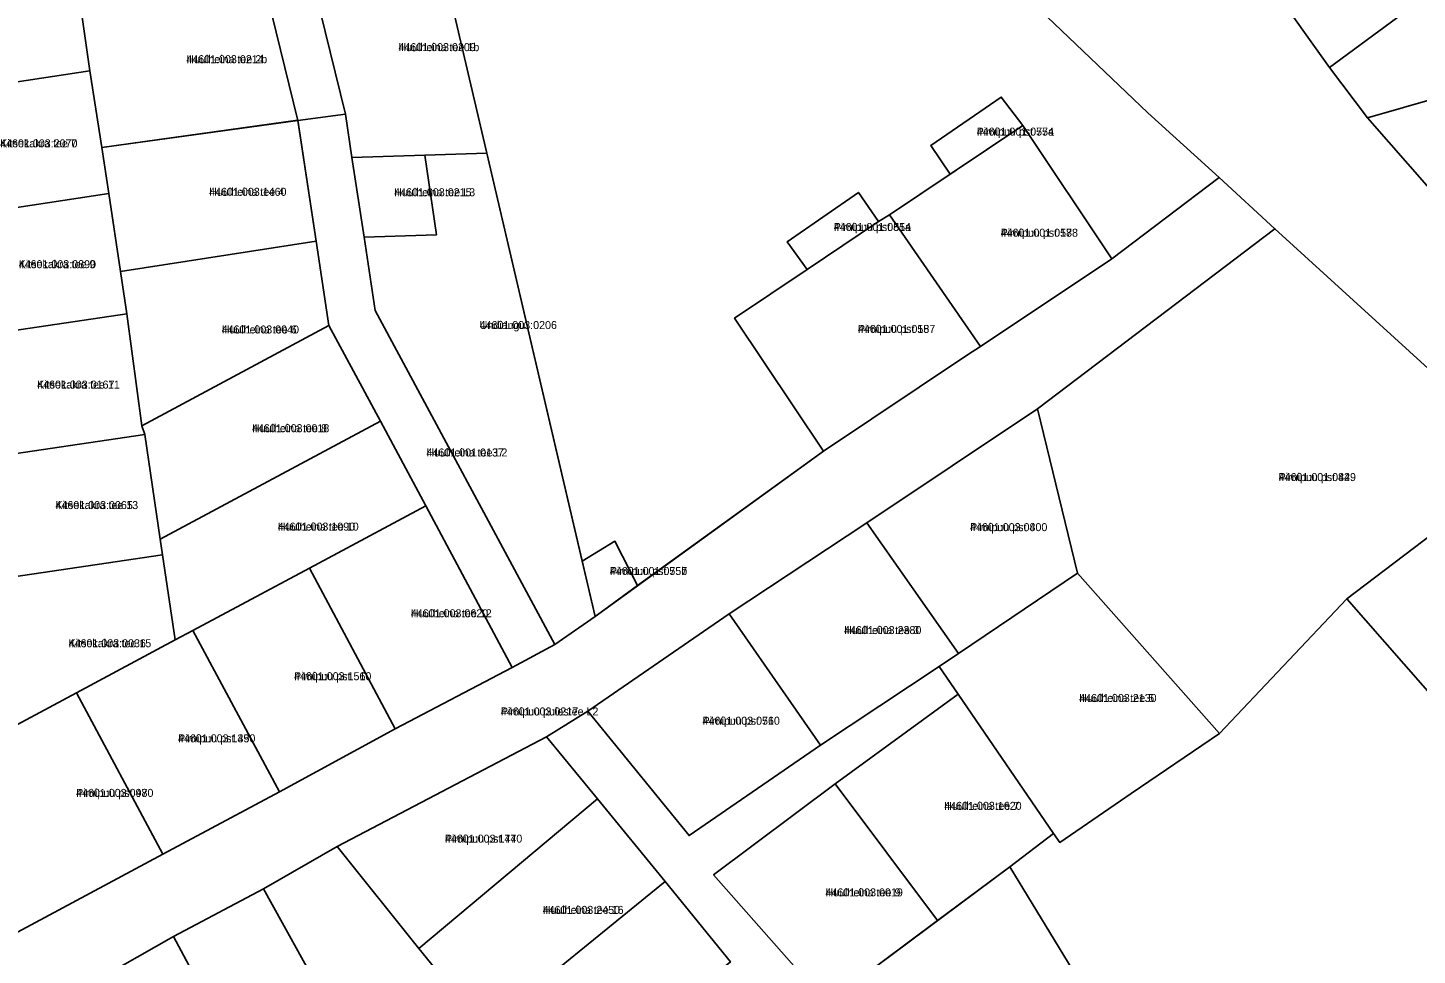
# Model space of a CAD drawing. Extents: x 551843 to 558501, y 6589003 to 6595718.
# Drawn here: x 553458.8 to 553719.3, y 6593624.3 to 6593798.2 of the extents above; entities that cross this region are included whole.
import ezdxf

# ---------------------------------------------------------------- set-up
doc = ezdxf.new("R2010")
doc.units = 0
for name, color, linetype in [('L_AADRESS', 7, 'Continuous'), ('PIIR', 7, 'Continuous'), ('TUNNUS', 7, 'Continuous')]:
    doc.layers.add(name, color=color, linetype=linetype)

msp = doc.modelspace()

# ---------------------------------------------------------------- linework, layer by layer
at = {"layer": 'PIIR'}
for points in [[(553514.88, 6593903.23), (553507.01, 6593937.53), (553542.86, 6593955.37), (553636.48, 6593813.23), (553668.84, 6593782.29), (553682.2, 6593770.11), (553662.08, 6593754.91), (553645.43, 6593779.86), (553641.35, 6593785.23), (553628.15, 6593776.12), (553631.77, 6593770.74), (553620.41, 6593763.16), (553618.37, 6593761.87), (553614.56, 6593767.34), (553601.23, 6593758.1), (553604.99, 6593752.88), (553591.37, 6593743.76), (553608.02, 6593718.81), (553573.18, 6593693.61), (553568.93, 6593701.92), (553562.79, 6593698.22), (553544.92, 6593774.7), (553535.42, 6593815.33), (553523, 6593868.46)], [(553492.7, 6593835.84), (553497.56, 6593844.41), (553505.32, 6593846.51), (553509.29, 6593831.88), (553506.64, 6593830.09), (553511.74, 6593809.27), (553518.39, 6593782.01), (553509.5, 6593780.83), (553502.99, 6593807.38), (553497.7, 6593828.94), (553494.74, 6593828.32)], [(553692.18, 6593805.9), (553712.78, 6593821.28), (553730.01, 6593834.09), (553741.11, 6593818.98), (553702.89, 6593790.78)], [(553741.11, 6593818.98), (553758.61, 6593795.24), (553710.04, 6593781.31), (553702.89, 6593790.78)], [(553535.42, 6593815.33), (553544.92, 6593774.7), (553533.27, 6593774.3), (553519.62, 6593773.88), (553518.39, 6593782.01), (553511.74, 6593809.27)], [(553430.62, 6593806.89), (553467.23, 6593812.98), (553468.8, 6593801.92), (553470.45, 6593790.14), (553433.32, 6593784.52)], [(553502.99, 6593807.38), (553509.5, 6593780.83), (553472.74, 6593775.77), (553470.45, 6593790.14), (553468.8, 6593801.92)], [(553470.45, 6593790.14), (553472.74, 6593775.77), (553474.02, 6593767.15), (553436.6, 6593761.45), (553433.32, 6593784.52)], [(553645.43, 6593779.86), (553631.77, 6593770.74), (553628.15, 6593776.12), (553641.35, 6593785.23)], [(553509.49, 6593780.87), (553512.89, 6593758.2), (553476.25, 6593752.53), (553474.02, 6593767.15), (553472.74, 6593775.77)], [(553512.89, 6593758.2), (553509.5, 6593780.83), (553518.39, 6593782.01), (553519.62, 6593773.88), (553521.89, 6593758.95), (553523.96, 6593745.19), (553557.67, 6593682.56), (553549.67, 6593678.28), (553533.46, 6593708.56), (553524.95, 6593724.42), (553515.3, 6593742.41)], [(553662.08, 6593754.91), (553637.47, 6593738.47), (553620.41, 6593763.16), (553645.43, 6593779.86)], [(553533.27, 6593774.3), (553535.46, 6593759.37), (553521.89, 6593758.95), (553519.62, 6593773.88)], [(553533.27, 6593774.3), (553544.92, 6593774.7), (553565.22, 6593687.84), (553557.67, 6593682.56), (553523.96, 6593745.19), (553521.89, 6593758.95), (553535.46, 6593759.37)], [(553436.6, 6593761.45), (553474.02, 6593767.15), (553476.25, 6593752.53), (553477.43, 6593744.57), (553440.63, 6593739.12)], [(553604.99, 6593752.88), (553601.23, 6593758.1), (553614.56, 6593767.34), (553618.37, 6593761.87)], [(553620.41, 6593763.16), (553637.47, 6593738.47), (553635.05, 6593736.86), (553608.02, 6593718.81), (553591.37, 6593743.76), (553604.99, 6593752.88), (553618.37, 6593761.87)], [(553648.17, 6593726.77), (553692.68, 6593760.54), (553740.33, 6593717.08), (553706.18, 6593691.1), (553682.25, 6593665.88), (553655.66, 6593695.97)], [(553512.89, 6593758.2), (553515.3, 6593742.41), (553480.21, 6593723.58), (553477.43, 6593744.57), (553476.25, 6593752.53)], [(553443.97, 6593716.53), (553440.63, 6593739.12), (553477.43, 6593744.57), (553480.21, 6593723.58), (553480.76, 6593721.97)], [(553480.76, 6593721.97), (553480.21, 6593723.58), (553515.3, 6593742.41), (553524.95, 6593724.42), (553483.66, 6593702.32)], [(553655.66, 6593695.97), (553633.31, 6593680.87), (553616.16, 6593705.37), (553648.17, 6593726.77)], [(553533.46, 6593708.56), (553511.64, 6593696.87), (553489.8, 6593685.2), (553486.46, 6593683.41), (553484.1, 6593699.37), (553483.66, 6593702.32), (553524.95, 6593724.42)], [(553443.97, 6593716.53), (553480.76, 6593721.97), (553483.66, 6593702.32), (553484.1, 6593699.37), (553447.31, 6593693.94)], [(553706.18, 6593691.1), (553740.33, 6593717.08), (553760.4, 6593695.25), (553727.55, 6593666.75)], [(553527.71, 6593666.74), (553511.64, 6593696.87), (553533.46, 6593708.56), (553549.67, 6593678.28)], [(553590.37, 6593688.32), (553616.16, 6593705.37), (553633.31, 6593680.87), (553629.72, 6593678.45), (553607.45, 6593663.66)], [(553565.22, 6593687.84), (553562.79, 6593698.22), (553568.93, 6593701.92), (553573.18, 6593693.6)], [(553484.1, 6593699.37), (553486.46, 6593683.41), (553467.99, 6593673.52), (553451.6, 6593664.73), (553447.31, 6593693.94)], [(553527.71, 6593666.74), (553506.01, 6593654.92), (553489.8, 6593685.2), (553511.64, 6593696.87)], [(553633.31, 6593680.87), (553655.66, 6593695.97), (553682.25, 6593665.88), (553665.73, 6593654.61), (553652.31, 6593645.45), (553651.15, 6593647.15), (553634.23, 6593671.86), (553629.72, 6593678.45)], [(553642.95, 6593640.9), (553651.15, 6593647.15), (553652.31, 6593645.45), (553665.73, 6593654.61), (553682.25, 6593665.88), (553706.18, 6593691.1), (553727.55, 6593666.75), (553740.49, 6593651.51), (553753.74, 6593636.43), (553762.31, 6593626.44), (553803.44, 6593644.47), (553829.2, 6593610.91), (553852.28, 6593578.7), (553731.4, 6593518.62), (553696.7, 6593564.49), (553681.11, 6593583.74), (553684.34, 6593586.4), (553671.35, 6593603.22), (553668.55, 6593601.29), (553655.51, 6593620.23)], [(553607.45, 6593663.66), (553582.84, 6593646.72), (553563.86, 6593670.06), (553590.37, 6593688.32)], [(553484.19, 6593643.24), (553467.99, 6593673.52), (553486.46, 6593683.41), (553489.8, 6593685.2), (553506.01, 6593654.92)], [(553456.92, 6593628.62), (553451.6, 6593664.73), (553467.99, 6593673.52), (553484.19, 6593643.24)], [(553633.29, 6593673.23), (553651.15, 6593647.15), (553642.95, 6593640.9), (553629.39, 6593630.84), (553610.19, 6593656.43)], [(553565.66, 6593653.61), (553532.13, 6593625.56), (553516.86, 6593644.69), (553556.12, 6593665.26)], [(553610.19, 6593656.43), (553629.39, 6593630.84), (553608.64, 6593615.29), (553587.41, 6593639.36)], [(553565.66, 6593653.61), (553578.32, 6593638.11), (553544.39, 6593610.49), (553532.13, 6593625.56)], [(553503.05, 6593636.73), (553516.86, 6593644.69), (553532.13, 6593625.56), (553544.39, 6593610.49), (553545.17, 6593609.54), (553530.83, 6593601.86), (553524.02, 6593598.81)], [(553642.95, 6593640.9), (553655.51, 6593620.23), (553622.78, 6593597.69), (553608.64, 6593615.29)], [(553545.17, 6593609.54), (553544.39, 6593610.49), (553578.32, 6593638.11), (553590.58, 6593623.04), (553556.65, 6593595.42)], [(553503.05, 6593636.73), (553524.02, 6593598.81), (553512.47, 6593592.6), (553506.67, 6593589.45), (553486.18, 6593627.79)], [(553469.35, 6593618.26), (553486.18, 6593627.79), (553506.67, 6593589.45), (553495.03, 6593582.69), (553489.88, 6593579.92)]]:
    msp.add_lwpolyline(points, close=True, dxfattribs=at)
for points in [[(553692.18, 6593805.9), (553702.89, 6593790.78), (553710.04, 6593781.31), (553721.57, 6593768.11), (553784.72, 6593695.82), (553773.88, 6593783.39), (553783.85, 6593784.58), (553786.09, 6593767.59), (553788.55, 6593748.98), (553791.01, 6593730.37), (553793.55, 6593711.51), (553796.03, 6593693.39), (553797.95, 6593674), (553801.52, 6593668.77), (553816.61, 6593652.09), (553803.44, 6593644.47), (553786.46, 6593665.16), (553772.78, 6593680.33), (553760.4, 6593695.25), (553740.33, 6593717.08), (553692.68, 6593760.54), (553682.2, 6593770.11), (553668.84, 6593782.29), (553636.48, 6593813.23)], [(553721.57, 6593768.11), (553710.04, 6593781.31), (553758.61, 6593795.24)], [(553456.92, 6593628.62), (553484.19, 6593643.24), (553506.01, 6593654.92), (553527.71, 6593666.74), (553549.67, 6593678.28), (553557.67, 6593682.56), (553565.22, 6593687.84), (553608.02, 6593718.81), (553635.05, 6593736.86), (553637.47, 6593738.47), (553662.08, 6593754.91), (553682.2, 6593770.11), (553692.68, 6593760.54), (553648.17, 6593726.77), (553616.16, 6593705.37), (553590.37, 6593688.32), (553563.86, 6593670.06), (553556.12, 6593665.26), (553516.86, 6593644.69), (553503.05, 6593636.73), (553486.18, 6593627.79), (553469.35, 6593618.26)], [(553590.58, 6593623.04), (553578.32, 6593638.11), (553565.66, 6593653.61), (553556.12, 6593665.26), (553563.86, 6593670.06), (553582.84, 6593646.72), (553607.45, 6593663.66), (553629.72, 6593678.45), (553633.29, 6593673.23), (553610.19, 6593656.43), (553587.41, 6593639.36), (553608.64, 6593615.29)]]:
    msp.add_lwpolyline(points, dxfattribs=at)

# ---------------------------------------------------------------- texts
at = {"layer": 'L_AADRESS'}
for s, p in [('Huulheina tee 1b', (553528.33, 6593793.83)), ('Huulheina tee 2b', (553488.56, 6593791.57)), ('Pirnipuu pst 57a', (553636.74, 6593777.99)), ('Kitsekakra tee 7', (553453.65, 6593775.79)), ('Huulheina tee 4', (553492.85, 6593766.7)), ('Huulheina tee L3', (553527.54, 6593766.62)), ('Pirnipuu pst 55a', (553609.94, 6593760.11)), ('Pirnipuu pst 57', (553641.24, 6593759.03)), ('Kitsekakra tee 9', (553457.13, 6593753.13)), ('Huulheina tee 6', (553495.19, 6593740.89)), ('Undiaugu', (553543.55, 6593741.72)), ('Pirnipuu pst 55', (553614.48, 6593740.99)), ('Kitsekakra tee 11', (553460.59, 6593730.55)), ('Huulheina tee 8', (553500.87, 6593722.37)), ('Huulheina tee L2', (553533.59, 6593717.82)), ('Pirnipuu pst 82', (553693.36, 6593713.21)), ('Kitsekakra tee 13', (553464.03, 6593707.96)), ('Huulheina tee 10', (553505.71, 6593703.92)), ('Pirnipuu pst 80', (553635.5, 6593703.82)), ('Pirnipuu pst 55b', (553567.98, 6593695.6)), ('Huulheina tee 12', (553530.66, 6593687.67)), ('Huulheina tee 3', (553611.88, 6593684.52)), ('Kitsekakra tee 15', (553466.49, 6593682.05)), ('Pirnipuu pst 51', (553508.75, 6593675.87)), ('Huulheina tee 5', (553655.98, 6593671.78)), ('Pirnipuu puiestee L2', (553547.54, 6593669.26)), ('Pirnipuu pst 76', (553585.35, 6593667.52)), ('Pirnipuu pst 49', (553487, 6593664.22)), ('Pirnipuu pst 47', (553467.89, 6593653.99)), ('Huulheina tee 7', (553630.67, 6593651.56)), ('Pirnipuu pst 74', (553537.05, 6593645.41)), ('Huulheina tee 9', (553608.4, 6593635.33)), ('Huulheina tee 16', (553555.38, 6593632.05))]:
    msp.add_text(s, height=1.5, dxfattribs=at).set_placement(p)
at = {"layer": 'TUNNUS'}
for s, p in [('44601:003:0209', (553528.33, 6593793.83)), ('44601:003:0214', (553488.56, 6593791.57)), ('44601:001:0754', (553636.74, 6593777.99)), ('44601:003:2070', (553453.65, 6593775.79)), ('44601:003:1460', (553492.85, 6593766.7)), ('44601:003:0215', (553527.54, 6593766.62)), ('44601:001:0814', (553609.94, 6593760.11)), ('44601:001:0188', (553641.24, 6593759.03)), ('44601:003:0890', (553457.13, 6593753.13)), ('44601:003:0040', (553495.19, 6593740.89)), ('44601:003:0206', (553543.55, 6593741.72)), ('44601:001:0187', (553614.48, 6593740.99)), ('44601:003:0167', (553460.59, 6593730.55)), ('44601:003:0018', (553500.87, 6593722.37)), ('44601:001:0137', (553533.59, 6593717.82)), ('44601:001:0449', (553693.36, 6593713.21)), ('44601:003:0065', (553464.03, 6593707.96)), ('44601:003:1090', (553505.71, 6593703.92)), ('44601:003:0400', (553635.5, 6593703.82)), ('44601:001:0757', (553567.98, 6593695.6)), ('44601:003:0620', (553530.66, 6593687.67)), ('44601:003:2380', (553611.88, 6593684.52)), ('44601:003:0036', (553466.49, 6593682.05)), ('44601:003:1560', (553508.75, 6593675.87)), ('44601:003:2130', (553655.98, 6593671.78)), ('44601:003:0217', (553547.54, 6593669.26)), ('44601:003:0510', (553585.35, 6593667.52)), ('44601:003:1350', (553487, 6593664.22)), ('44601:003:0980', (553467.89, 6593653.99)), ('44601:003:1620', (553630.67, 6593651.56)), ('44601:003:1470', (553537.05, 6593645.41)), ('44601:003:0019', (553608.4, 6593635.33)), ('44601:003:2450', (553555.38, 6593632.05))]:
    msp.add_text(s, height=1.5, dxfattribs=at).set_placement(p)

doc.saveas('drawing.dxf')
